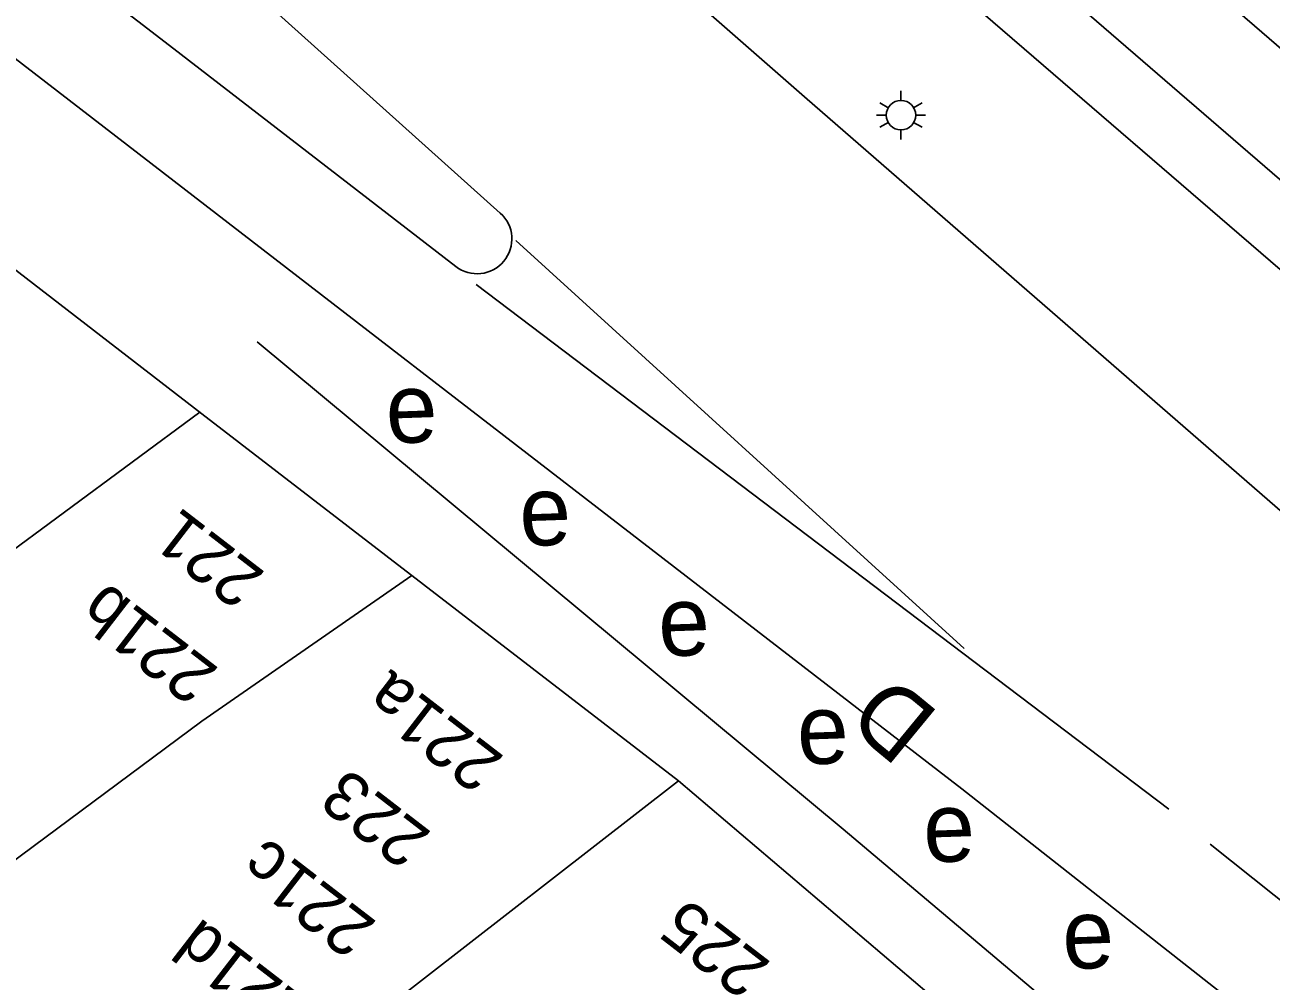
# Model space of a CAD drawing. Extents: x 81617 to 82144, y 454649 to 455150.
# Drawn here: x 81697.46 to 81715.37, y 454706.31 to 454720.05 of the extents above; entities that cross this region are included whole.
import ezdxf

# ---------------------------------------------------------------- set-up
doc = ezdxf.new("R2010")
doc.units = 0
doc.layers.add('B-WE-OG-TOPOGRAFIE-G', color=7, linetype='Continuous')
doc.layers.add('B-WE-VW-MARKERING-G', color=7, linetype='Continuous')

msp = doc.modelspace()

# ---------------------------------------------------------------- linework, layer by layer
at = {"layer": 'B-WE-OG-TOPOGRAFIE-G'}
for p, q in [((81703.871, 454726.575), (81730.855, 454703.267)), ((81699.533, 454719.756), (81696.366, 454722.2)), ((81704.288, 454717.349), (81700.649, 454720.614)), ((81710.046, 454718.956), (81710.046, 454719.106)), ((81709.873, 454718.856), (81709.743, 454718.931)), ((81710.219, 454718.856), (81710.349, 454718.931)), ((81709.834, 454718.756), (81709.693, 454718.756)), ((81709.873, 454718.656), (81709.743, 454718.581)), ((81710.219, 454718.656), (81710.349, 454718.581)), ((81710.399, 454718.756), (81710.258, 454718.756)), ((81710.046, 454718.556), (81710.046, 454718.406)), ((81700.793, 454715.497), (81709.216, 454708.492)), ((81690.199, 454707.264), (81699.968, 454714.488)), ((81700, 454710.044), (81703.019, 454712.136)), ((81694.423, 454705.904), (81700, 454710.044)), ((81700, 454703.869), (81706.847, 454709.185)), ((81709.216, 454708.492), (81722.53, 454697.265))]:
    msp.add_line(p, q, dxfattribs=at)
for points in [[(81711.061, 454723.559), (81760.224, 454681.093)], [(81710.123, 454722.473), (81759.251, 454680.037)], [(81704.937, 454722.283), (81708.662, 454719.021), (81727.987, 454702.211)], [(81695.133, 454721.257), (81710.923, 454709.073), (81719.683, 454702.175)], [(81699.533, 454719.756), (81703.649, 454716.581)], [(81681.659, 454710.717), (81681.638, 454710.746), (81691.36, 454719.373), (81693.506, 454719.47), (81696.504, 454717.158), (81700, 454714.463)], [(81700, 454714.463), (81706.847, 454709.185), (81714.953, 454702.287), (81717.886, 454699.79), (81719.1, 454698.758), (81723.254, 454694.862)]]:
    msp.add_lwpolyline(points, dxfattribs=at)
msp.add_circle((81710.046, 454718.756), 0.212, dxfattribs=at)
msp.add_arc((81703.954, 454716.976), 0.5, 232.3459, 48.0994, dxfattribs=at)
at = {"layer": 'B-WE-VW-MARKERING-G'}
for p, q in [((81710.955, 454711.087), (81704.511, 454716.954)), ((81703.939, 454716.32), (81711.095, 454710.9)), ((81711.095, 454710.9), (81713.896, 454708.778))]:
    msp.add_line(p, q, dxfattribs=at)
msp.add_lwpolyline([(81754.205, 454674.562), (81750.269, 454678.038), (81736.422, 454689.987), (81726.94, 454698.352), (81714.491, 454708.275)], dxfattribs=at)

# ---------------------------------------------------------------- texts
at = {"layer": 'B-WE-OG-TOPOGRAFIE-G'}
for s, height, rotation, p in [('e', 1, 1.9612, (81702.656, 454714.035)), ('e', 1, 1.9612, (81704.576, 454712.559)), ('221', 0.7, 142.3773, (81700.928, 454712.171)), ('221b', 0.7, 142.3773, (81700.261, 454710.792)), ('e', 1, 1.9612, (81706.571, 454710.973)), ('221a', 0.7, 142.3587, (81704.363, 454709.524)), ('D', 1, 140.5274, (81710.622, 454710.145)), ('e', 1, 1.9612, (81708.566, 454709.418)), ('223', 0.7, 142.3587, (81703.318, 454708.435)), ('e', 1, 1.9612, (81710.38, 454708.011)), ('221c', 0.7, 142.3587, (81702.532, 454707.148)), ('225', 0.7, 142.3587, (81708.196, 454706.566)), ('221d', 0.7, 142.3587, (81701.614, 454705.96)), ('e', 1, 1.9612, (81712.379, 454706.477))]:
    msp.add_text(s, height=height, rotation=rotation, dxfattribs=at).set_placement(p)

doc.saveas('drawing.dxf')
